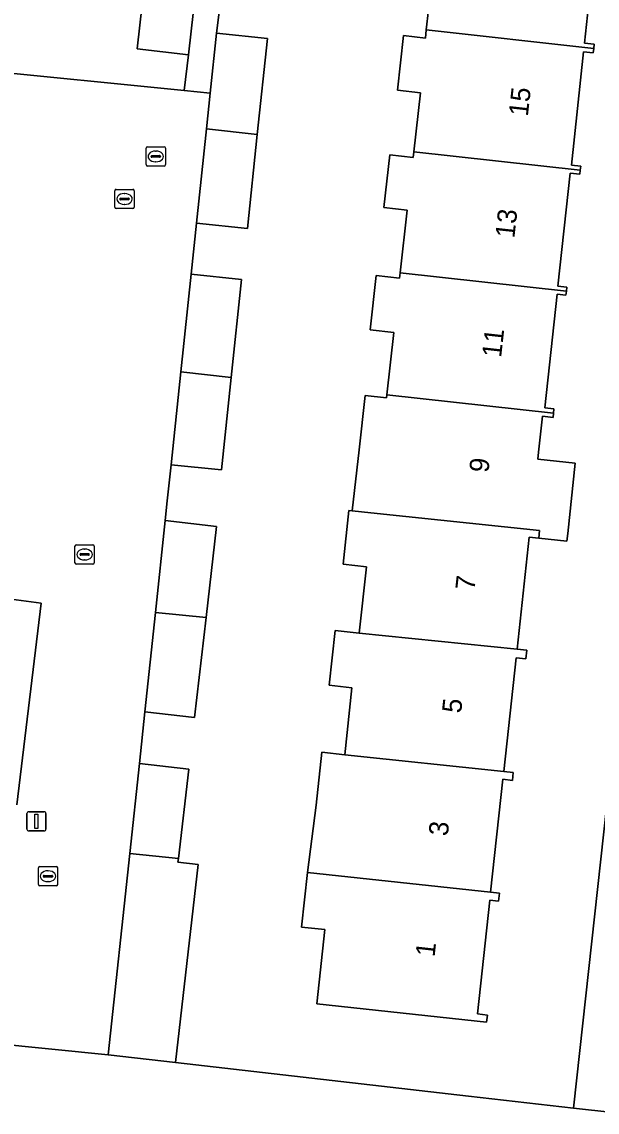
# Model space of a CAD drawing. Extents: x 162082 to 163401, y 388089 to 388636.
# Drawn here: x 162848.7 to 162878.5, y 388468.3 to 388524.8 of the extents above; entities that cross this region are included whole.
import ezdxf

# ---------------------------------------------------------------- set-up
doc = ezdxf.new("R2010")
doc.units = 0
for name, color, linetype in [('IMGEO_Erf', 7, 'Continuous'), ('IMGEO_Kolk', 7, 'Continuous'), ('IMGEO_Lichtmast', 7, 'Continuous'), ('IMGEO_Muur', 7, 'Continuous'), ('IMGEO_Pand', 7, 'Continuous'), ('IMGEO_Pand_nummerreeks', 7, 'Continuous'), ('IMGEO_Rijbaan_lokaal_open', 7, 'Continuous'), ('IMGEO_Rioolput', 7, 'Continuous'), ('IMGEO_Voetpad_open', 7, 'Continuous')]:
    doc.layers.add(name, color=color, linetype=linetype)

msp = doc.modelspace()

# ---------------------------------------------------------------- linework, layer by layer
at = {"layer": 'IMGEO_Erf'}
for points in [[(162860.477, 388537.833), (162858.755, 388524.231), (162861.392, 388523.953), (162860.867, 388518.975), (162860.354, 388514.105), (162857.718, 388514.382), (162857.44, 388511.746), (162860.052, 388511.471), (162859.516, 388506.387), (162859.012, 388501.597), (162856.4, 388501.872), (162856.203, 388500), (162856.096, 388498.983), (162858.763, 388498.676), (162858.219, 388493.947), (162857.624, 388488.771), (162855.052, 388489.067), (162854.77, 388486.392), (162857.316, 388486.099), (162856.782, 388481.466), (162856.76, 388481.272), (162857.808, 388481.152), (162856.628, 388470.904), (162871.805, 388469.165), (162877.252, 388468.541), (162880.7, 388500)], [(162878.44, 388529.523), (162877.814, 388523.71), (162878.314, 388523.656), (162878.29, 388523.435), (162878.266, 388523.215), (162877.768, 388523.269), (162877.134, 388517.381), (162877.618, 388517.329), (162877.596, 388517.126), (162877.573, 388516.918), (162877.066, 388516.972), (162876.436, 388511.126), (162876.898, 388511.076), (162876.875, 388510.868), (162876.853, 388510.662), (162876.393, 388510.712), (162875.758, 388504.817), (162876.231, 388504.766), (162876.207, 388504.542), (162876.184, 388504.322), (162875.643, 388504.381), (162875.44, 388502.513), (162875.402, 388502.164), (162877.337, 388501.954), (162876.945, 388498.307), (162876.903, 388497.915), (162875.447, 388498.07), (162874.952, 388498.124), (162874.322, 388492.311), (162874.824, 388492.257), (162874.776, 388491.816), (162874.28, 388491.87), (162873.642, 388485.983), (162874.128, 388485.93), (162874.083, 388485.519), (162873.578, 388485.573), (162872.945, 388479.729), (162873.406, 388479.676), (162873.365, 388479.263), (162872.905, 388479.313), (162872.266, 388473.418), (162872.783, 388473.362), (162872.744, 388472.997), (162863.958, 388473.949), (162864.373, 388477.783), (162863.158, 388477.914), (162863.466, 388480.749), (162863.921, 388484.234), (162864.218, 388486.974), (162865.396, 388486.846), (162865.772, 388490.32), (162864.595, 388490.447), (162864.902, 388493.277), (162866.144, 388493.142), (162866.517, 388496.587), (162865.312, 388496.718), (162865.612, 388499.494), (162865.78, 388499.476), (162866.137, 388502.646), (162866.454, 388505.459), (162867.558, 388505.334), (162867.576, 388505.496), (162867.939, 388508.715), (162866.707, 388508.854), (162867.026, 388511.676), (162868.235, 388511.54), (162868.267, 388511.82), (162868.631, 388515.054), (162867.428, 388515.19), (162867.736, 388517.916), (162868.941, 388517.78), (162868.975, 388518.079), (162869.32, 388521.14), (162868.123, 388521.275), (162868.442, 388524.102), (162869.572, 388523.974), (162869.619, 388524.394), (162869.973, 388527.53)], [(162847.115, 388528.959), (162846.345, 388522.331), (162857.085, 388521.261), (162857.298, 388523.103), (162854.642, 388523.409), (162855.165, 388528.025)], [(162848.412, 388484.25), (162849.684, 388494.705), (162848.127, 388494.898)]]:
    msp.add_lwpolyline(points, dxfattribs=at)
at = {"layer": 'IMGEO_Kolk'}
for p, q in [((162853.491, 388515.211), (162853.491, 388516.063)), ((162853.566, 388516.137), (162854.418, 388516.137)), ((162854.492, 388516.063), (162854.492, 388515.211)), ((162853.75, 388515.631), (162853.75, 388515.643)), ((162854.188, 388515.594), (162853.79, 388515.594)), ((162853.793, 388515.68), (162854.191, 388515.68)), ((162853.979, 388515.917), (162854.004, 388515.917)), ((162854.234, 388515.643), (162854.234, 388515.631)), ((162854.418, 388515.137), (162853.566, 388515.137)), ((162854.002, 388515.357), (162853.977, 388515.357)), ((162851.427, 388496.794), (162851.427, 388497.646)), ((162851.502, 388497.72), (162852.354, 388497.72)), ((162851.915, 388497.5), (162851.94, 388497.5)), ((162852.428, 388497.646), (162852.428, 388496.794)), ((162851.686, 388497.214), (162851.686, 388497.226)), ((162852.124, 388497.177), (162851.726, 388497.177)), ((162851.729, 388497.263), (162852.127, 388497.263)), ((162851.938, 388496.94), (162851.913, 388496.94)), ((162852.17, 388497.226), (162852.17, 388497.214)), ((162852.354, 388496.72), (162851.502, 388496.72)), ((162849.529, 388480.126), (162849.529, 388480.978)), ((162849.604, 388481.052), (162850.456, 388481.052)), ((162850.53, 388480.978), (162850.53, 388480.126)), ((162849.788, 388480.546), (162849.788, 388480.558)), ((162850.226, 388480.509), (162849.828, 388480.509)), ((162849.831, 388480.595), (162850.229, 388480.595)), ((162850.017, 388480.832), (162850.042, 388480.832)), ((162850.272, 388480.558), (162850.272, 388480.546)), ((162850.456, 388480.052), (162849.604, 388480.052)), ((162850.04, 388480.272), (162850.015, 388480.272))]:
    msp.add_line(p, q, dxfattribs=at)
for points in [[(162853.491, 388515.211), (162853.491, 388516.063)], [(162853.566, 388516.137), (162854.418, 388516.137)], [(162854.492, 388516.063), (162854.492, 388515.211)], [(162854.418, 388515.137), (162853.566, 388515.137)], [(162851.427, 388496.794), (162851.427, 388497.646)], [(162851.502, 388497.72), (162852.354, 388497.72)], [(162852.428, 388497.646), (162852.428, 388496.794)], [(162852.354, 388496.72), (162851.502, 388496.72)], [(162849.529, 388480.126), (162849.529, 388480.978)], [(162849.604, 388481.052), (162850.456, 388481.052)], [(162850.53, 388480.978), (162850.53, 388480.126)], [(162850.456, 388480.052), (162849.604, 388480.052)]]:
    msp.add_lwpolyline(points, dxfattribs=at)
for centre, radius, start, end in [((162853.568, 388516.061), 0.0765, 91.552, 178.448), ((162853.568, 388516.061), 0.0765, 91.552, 178.448), ((162854.416, 388516.061), 0.0765, 1.552, 88.448), ((162854.416, 388516.061), 0.0765, 1.552, 88.448), ((162853.79, 388515.64), 0.0403, 85.8775, 175.7526), ((162853.787, 388515.63), 0.0366, 178.938, 274.7102), ((162854.191, 388515.637), 0.043, 264.8664, 352.4533), ((162854.195, 388515.642), 0.0386, 1.7309, 96.639), ((162853.568, 388515.213), 0.0765, 181.552, 268.448), ((162853.568, 388515.213), 0.0765, 181.552, 268.448), ((162854.416, 388515.213), 0.0765, 271.552, 358.448), ((162854.416, 388515.213), 0.0765, 271.552, 358.448), ((162851.504, 388497.644), 0.0765, 91.552, 178.448), ((162851.504, 388497.644), 0.0765, 91.552, 178.448), ((162852.352, 388497.644), 0.0765, 1.552, 88.448), ((162852.352, 388497.644), 0.0765, 1.552, 88.448), ((162851.504, 388496.796), 0.0765, 181.552, 268.448), ((162851.504, 388496.796), 0.0765, 181.552, 268.448), ((162851.726, 388497.223), 0.0403, 85.8775, 175.7526), ((162851.723, 388497.213), 0.0366, 178.938, 274.7102), ((162852.127, 388497.22), 0.043, 264.8664, 352.4533), ((162852.131, 388497.225), 0.0386, 1.7309, 96.639), ((162852.352, 388496.796), 0.0765, 271.552, 358.448), ((162852.352, 388496.796), 0.0765, 271.552, 358.448), ((162849.606, 388480.976), 0.0765, 91.552, 178.448), ((162849.606, 388480.976), 0.0765, 91.552, 178.448), ((162850.454, 388480.976), 0.0765, 1.552, 88.448), ((162850.454, 388480.976), 0.0765, 1.552, 88.448), ((162849.828, 388480.555), 0.0403, 85.8775, 175.7526), ((162849.825, 388480.545), 0.0366, 178.938, 274.7102), ((162850.229, 388480.552), 0.043, 264.8664, 352.4533), ((162850.233, 388480.557), 0.0386, 1.7309, 96.639), ((162849.606, 388480.128), 0.0765, 181.552, 268.448), ((162849.606, 388480.128), 0.0765, 181.552, 268.448), ((162850.454, 388480.128), 0.0765, 271.552, 358.448), ((162850.454, 388480.128), 0.0765, 271.552, 358.448)]:
    msp.add_arc(centre, radius, start, end, dxfattribs=at)
for centre, major_axis, ratio, start_param, end_param in [((162853.978, 388515.637), (-0.387, 0.002), 0.722429, 4.712389, 7.853982), ((162854.003, 388515.637), (-0.39, 0.002), 0.717154, 1.570796, 4.712389), ((162851.914, 388497.22), (-0.387, 0.002), 0.722429, 4.712389, 7.853982), ((162851.939, 388497.22), (-0.39, 0.002), 0.717154, 1.570796, 4.712389), ((162850.016, 388480.552), (-0.387, 0.002), 0.722429, 4.712389, 7.853982), ((162850.041, 388480.552), (-0.39, 0.002), 0.717154, 1.570796, 4.712389)]:
    msp.add_ellipse(centre, major_axis=major_axis, ratio=ratio, start_param=start_param, end_param=end_param, dxfattribs=at)
at = {"layer": 'IMGEO_Lichtmast'}
for p, q in [((162848.935, 388482.996), (162848.935, 388483.796)), ((162848.935, 388483.796), (162848.935, 388482.996)), ((162849.035, 388483.896), (162849.825, 388483.896)), ((162849.825, 388483.896), (162849.035, 388483.896)), ((162849.925, 388483.796), (162849.925, 388482.996)), ((162849.925, 388482.996), (162849.925, 388483.796)), ((162849.825, 388482.896), (162849.035, 388482.896)), ((162849.035, 388482.896), (162849.825, 388482.896))]:
    msp.add_line(p, q, dxfattribs=at)
msp.add_lwpolyline([(162849.355, 388483.771), (162849.505, 388483.771), (162849.505, 388483.021), (162849.355, 388483.021), (162849.355, 388483.771)], dxfattribs=at)
for centre, start, end in [((162849.035, 388483.796), 90, 180), ((162849.035, 388483.796), 90, 180), ((162849.825, 388483.796), 0, 90), ((162849.825, 388483.796), 360, 90), ((162849.035, 388482.996), 180, 270), ((162849.035, 388482.996), 180, 270), ((162849.825, 388482.996), 270, 0), ((162849.825, 388482.996), 270, 0)]:
    msp.add_arc(centre, 0.1, start, end, dxfattribs=at)
at = {"layer": 'IMGEO_Muur'}
for points in [[(162848.127, 388494.898), (162849.684, 388494.705), (162848.412, 388484.25)], [(162871.805, 388469.165), (162856.628, 388470.904)]]:
    msp.add_lwpolyline(points, dxfattribs=at)
at = {"layer": 'IMGEO_Pand'}
for points in [[(162878.962, 388529.705), (162870.334, 388530.658), (162870.289, 388530.257), (162869.171, 388530.384), (162868.863, 388527.655), (162869.973, 388527.53), (162869.619, 388524.394), (162878.29, 388523.435), (162878.314, 388523.656), (162877.814, 388523.71), (162878.44, 388529.523), (162878.937, 388529.469)], [(162855.165, 388528.025), (162854.642, 388523.409), (162857.298, 388523.103), (162857.821, 388527.716)], [(162860.867, 388518.975), (162861.392, 388523.953), (162858.755, 388524.231), (162858.428, 388521.127), (162858.232, 388519.267)], [(162877.596, 388517.126), (162877.618, 388517.329), (162877.134, 388517.381), (162877.768, 388523.269), (162878.266, 388523.215), (162878.29, 388523.435), (162869.619, 388524.394), (162869.572, 388523.974), (162868.442, 388524.102), (162868.123, 388521.275), (162869.32, 388521.14), (162868.975, 388518.079)], [(162860.867, 388518.975), (162858.232, 388519.267), (162857.718, 388514.382), (162860.354, 388514.105)], [(162877.596, 388517.126), (162868.975, 388518.079), (162868.941, 388517.78), (162867.736, 388517.916), (162867.428, 388515.19), (162868.631, 388515.054), (162868.267, 388511.82), (162876.875, 388510.868), (162876.898, 388511.076), (162876.436, 388511.126), (162877.066, 388516.972), (162877.573, 388516.918)], [(162856.906, 388506.675), (162859.516, 388506.387), (162860.052, 388511.471), (162857.44, 388511.746)], [(162876.875, 388510.868), (162868.267, 388511.82), (162868.235, 388511.54), (162867.026, 388511.676), (162866.707, 388508.854), (162867.939, 388508.715), (162867.576, 388505.496), (162876.207, 388504.542), (162876.231, 388504.766), (162875.758, 388504.817), (162876.393, 388510.712), (162876.853, 388510.662)], [(162856.906, 388506.675), (162856.4, 388501.872), (162859.012, 388501.597), (162859.516, 388506.387)], [(162875.402, 388502.164), (162875.44, 388502.513), (162875.643, 388504.381), (162876.184, 388504.322), (162876.207, 388504.542), (162867.576, 388505.496), (162867.558, 388505.334), (162866.454, 388505.459), (162866.137, 388502.646), (162865.78, 388499.476), (162866.742, 388499.371), (162875.489, 388498.464), (162875.447, 388498.07), (162876.903, 388497.915), (162876.945, 388498.307), (162877.337, 388501.954)], [(162874.952, 388498.124), (162875.447, 388498.07), (162875.489, 388498.464), (162866.742, 388499.371), (162865.78, 388499.476), (162865.612, 388499.494), (162865.312, 388496.718), (162866.517, 388496.587), (162866.144, 388493.142), (162874.322, 388492.311)], [(162855.594, 388494.214), (162858.219, 388493.947), (162858.763, 388498.676), (162856.096, 388498.983)], [(162855.594, 388494.214), (162855.052, 388489.067), (162857.624, 388488.771), (162858.219, 388493.947)], [(162866.144, 388493.142), (162864.902, 388493.277), (162864.595, 388490.447), (162865.772, 388490.32), (162865.396, 388486.846), (162873.642, 388485.983), (162874.28, 388491.87), (162874.776, 388491.816), (162874.824, 388492.257), (162874.322, 388492.311)], [(162863.466, 388480.749), (162872.945, 388479.729), (162873.578, 388485.573), (162874.083, 388485.519), (162874.128, 388485.93), (162873.642, 388485.983), (162865.396, 388486.846), (162864.218, 388486.974), (162863.921, 388484.234)], [(162854.267, 388481.736), (162856.782, 388481.466), (162857.316, 388486.099), (162854.77, 388486.392)], [(162854.267, 388481.736), (162853.139, 388471.305), (162856.628, 388470.904), (162857.808, 388481.152), (162856.76, 388481.272), (162856.782, 388481.466)], [(162863.466, 388480.749), (162863.158, 388477.914), (162864.373, 388477.783), (162863.958, 388473.949), (162872.744, 388472.997), (162872.783, 388473.362), (162872.266, 388473.418), (162872.905, 388479.313), (162873.365, 388479.263), (162873.406, 388479.676), (162872.945, 388479.729)]]:
    msp.add_lwpolyline(points, close=True, dxfattribs=at)
at = {"layer": 'IMGEO_Rijbaan_lokaal_open'}
msp.add_lwpolyline([(162886.924, 388500), (162888.262, 388514.856), (162889.179, 388520.793), (162890.761, 388535.503), (162891.85, 388545.225), (162885.731, 388545.91), (162880.7, 388500), (162877.252, 388468.541), (162883.202, 388467.882)], close=True, dxfattribs=at)
for points in [[(162847.118, 388471.904), (162853.139, 388471.305), (162854.267, 388481.736), (162854.77, 388486.392), (162855.052, 388489.067), (162855.594, 388494.214), (162856.096, 388498.983), (162856.203, 388500), (162856.4, 388501.872), (162856.906, 388506.675), (162857.44, 388511.746), (162857.718, 388514.382), (162858.232, 388519.267), (162858.428, 388521.127), (162857.085, 388521.261), (162846.345, 388522.331)], [(162848.127, 388494.898), (162849.684, 388494.705), (162848.412, 388484.25)]]:
    msp.add_lwpolyline(points, dxfattribs=at)
at = {"layer": 'IMGEO_Rioolput'}
for p, q in [((162855.11, 388517.416), (162855.11, 388518.268)), ((162855.185, 388518.342), (162856.037, 388518.342)), ((162856.111, 388518.268), (162856.111, 388517.416)), ((162855.369, 388517.836), (162855.369, 388517.848)), ((162855.807, 388517.799), (162855.409, 388517.799)), ((162855.412, 388517.885), (162855.81, 388517.885)), ((162855.598, 388518.122), (162855.623, 388518.122)), ((162855.853, 388517.848), (162855.853, 388517.836)), ((162856.037, 388517.342), (162855.185, 388517.342)), ((162855.621, 388517.562), (162855.596, 388517.562))]:
    msp.add_line(p, q, dxfattribs=at)
for points in [[(162855.11, 388517.416), (162855.11, 388518.268)], [(162855.185, 388518.342), (162856.037, 388518.342)], [(162856.111, 388518.268), (162856.111, 388517.416)], [(162856.037, 388517.342), (162855.185, 388517.342)]]:
    msp.add_lwpolyline(points, dxfattribs=at)
for centre, radius, start, end in [((162855.187, 388518.266), 0.0765, 91.552, 178.448), ((162855.187, 388518.266), 0.0765, 91.552, 178.448), ((162856.035, 388518.266), 0.0765, 1.552, 88.448), ((162856.035, 388518.266), 0.0765, 1.552, 88.448), ((162855.409, 388517.845), 0.0403, 85.8775, 175.7526), ((162855.406, 388517.835), 0.0366, 178.938, 274.7102), ((162855.81, 388517.842), 0.043, 264.8664, 352.4533), ((162855.814, 388517.847), 0.0386, 1.7309, 96.639), ((162855.187, 388517.418), 0.0765, 181.552, 268.448), ((162855.187, 388517.418), 0.0765, 181.552, 268.448), ((162856.035, 388517.418), 0.0765, 271.552, 358.448), ((162856.035, 388517.418), 0.0765, 271.552, 358.448)]:
    msp.add_arc(centre, radius, start, end, dxfattribs=at)
for centre, major_axis, ratio, start_param, end_param in [((162855.597, 388517.842), (-0.387, 0.002), 0.722429, 4.712389, 7.853982), ((162855.622, 388517.842), (-0.39, 0.002), 0.717154, 1.570796, 4.712389)]:
    msp.add_ellipse(centre, major_axis=major_axis, ratio=ratio, start_param=start_param, end_param=end_param, dxfattribs=at)
at = {"layer": 'IMGEO_Voetpad_open'}
msp.add_lwpolyline([(162860.477, 388537.833), (162860.54, 388538.387), (162859.05, 388538.557), (162858.688, 388535.363), (162858.45, 388533.263), (162857.821, 388527.716), (162857.298, 388523.103), (162857.085, 388521.261), (162858.428, 388521.127), (162858.755, 388524.231)], close=True, dxfattribs=at)
for points in [[(162877.252, 388468.541), (162871.805, 388469.165), (162856.628, 388470.904), (162853.139, 388471.305), (162847.118, 388471.904), (162794.676, 388477.705), (162786.727, 388478.655), (162739.055, 388483.959)], [(162936.199, 388456.79), (162937.278, 388456.67), (162942.976, 388456.033), (162943.878, 388455.932), (162947.378, 388455.541), (162967.209, 388453.279), (162967.535, 388456.949), (162967.668, 388458.452), (162959.667, 388459.314), (162950.273, 388460.333), (162948.558, 388460.57), (162943.553, 388461.129), (162937.585, 388461.764), (162885.189, 388467.652), (162883.202, 388467.882), (162877.252, 388468.541)]]:
    msp.add_lwpolyline(points, dxfattribs=at)

# ---------------------------------------------------------------- texts
at = {"layer": 'IMGEO_Pand_nummerreeks'}
for s, rotation, p in [('15', 83.6814, (162874.877, 388519.888)), ('13', 83.6814, (162874.179, 388513.583)), ('11', 83.6814, (162873.494, 388507.391)), ('9', 83.6805, (162872.833, 388501.43)), ('7', 83.7951, (162872.114, 388495.334)), ('5', 83.7953, (162871.422, 388488.967)), ('3', 83.7953, (162870.729, 388482.601)), ('1', 83.7953, (162870.049, 388476.348))]:
    msp.add_text(s, height=1, rotation=rotation, dxfattribs=at).set_placement(p)

doc.saveas('drawing.dxf')
